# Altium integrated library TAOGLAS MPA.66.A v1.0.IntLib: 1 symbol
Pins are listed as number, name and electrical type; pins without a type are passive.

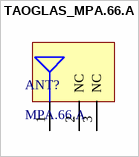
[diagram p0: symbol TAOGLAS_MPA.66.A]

## TAOGLAS_MPA.66.A
designator ANT?, comment MPA.66.A
5G/4G Cellular 600~6000MHz SMD Stamp Metal PIFA Antenna, 55*20*15mm; ComponentLibStatus: Created; MFG: Taoglas; Temp_High: +85C; Temp_Low: -40C
footprint TAOGLAS_MPA.66.A (5G/4G Cellular 600~6000MHz SMD Stamp Metal PIFA Antenna, 55*20*15mm)
pins: 1 RF FEED, 2 NC, 3 NC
